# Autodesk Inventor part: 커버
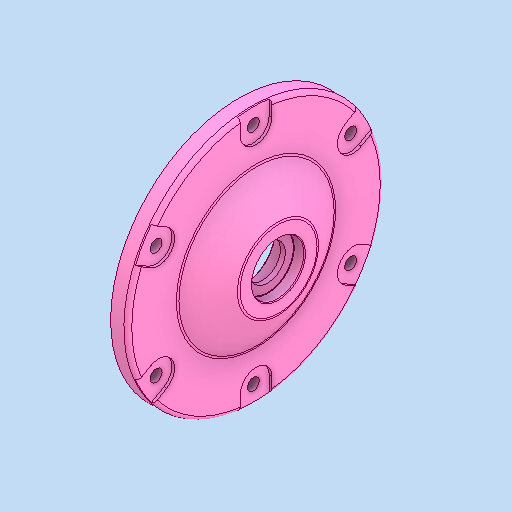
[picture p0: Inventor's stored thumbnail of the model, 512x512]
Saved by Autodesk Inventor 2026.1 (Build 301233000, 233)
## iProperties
Created: 2025-11
Part Number: 커버
Material: 알루미늄 6061
Document SubType Name: Modeling
Designer: PC-30
Density: 2.7 g/cm^3
Appearance: 기본값
Author: jhkim
Sending System: Autodesk Inventor 2026
Preprocessor: ST-DEVELOPER v20.1
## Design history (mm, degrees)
feature "솔리드1"
node "솔리드2"
